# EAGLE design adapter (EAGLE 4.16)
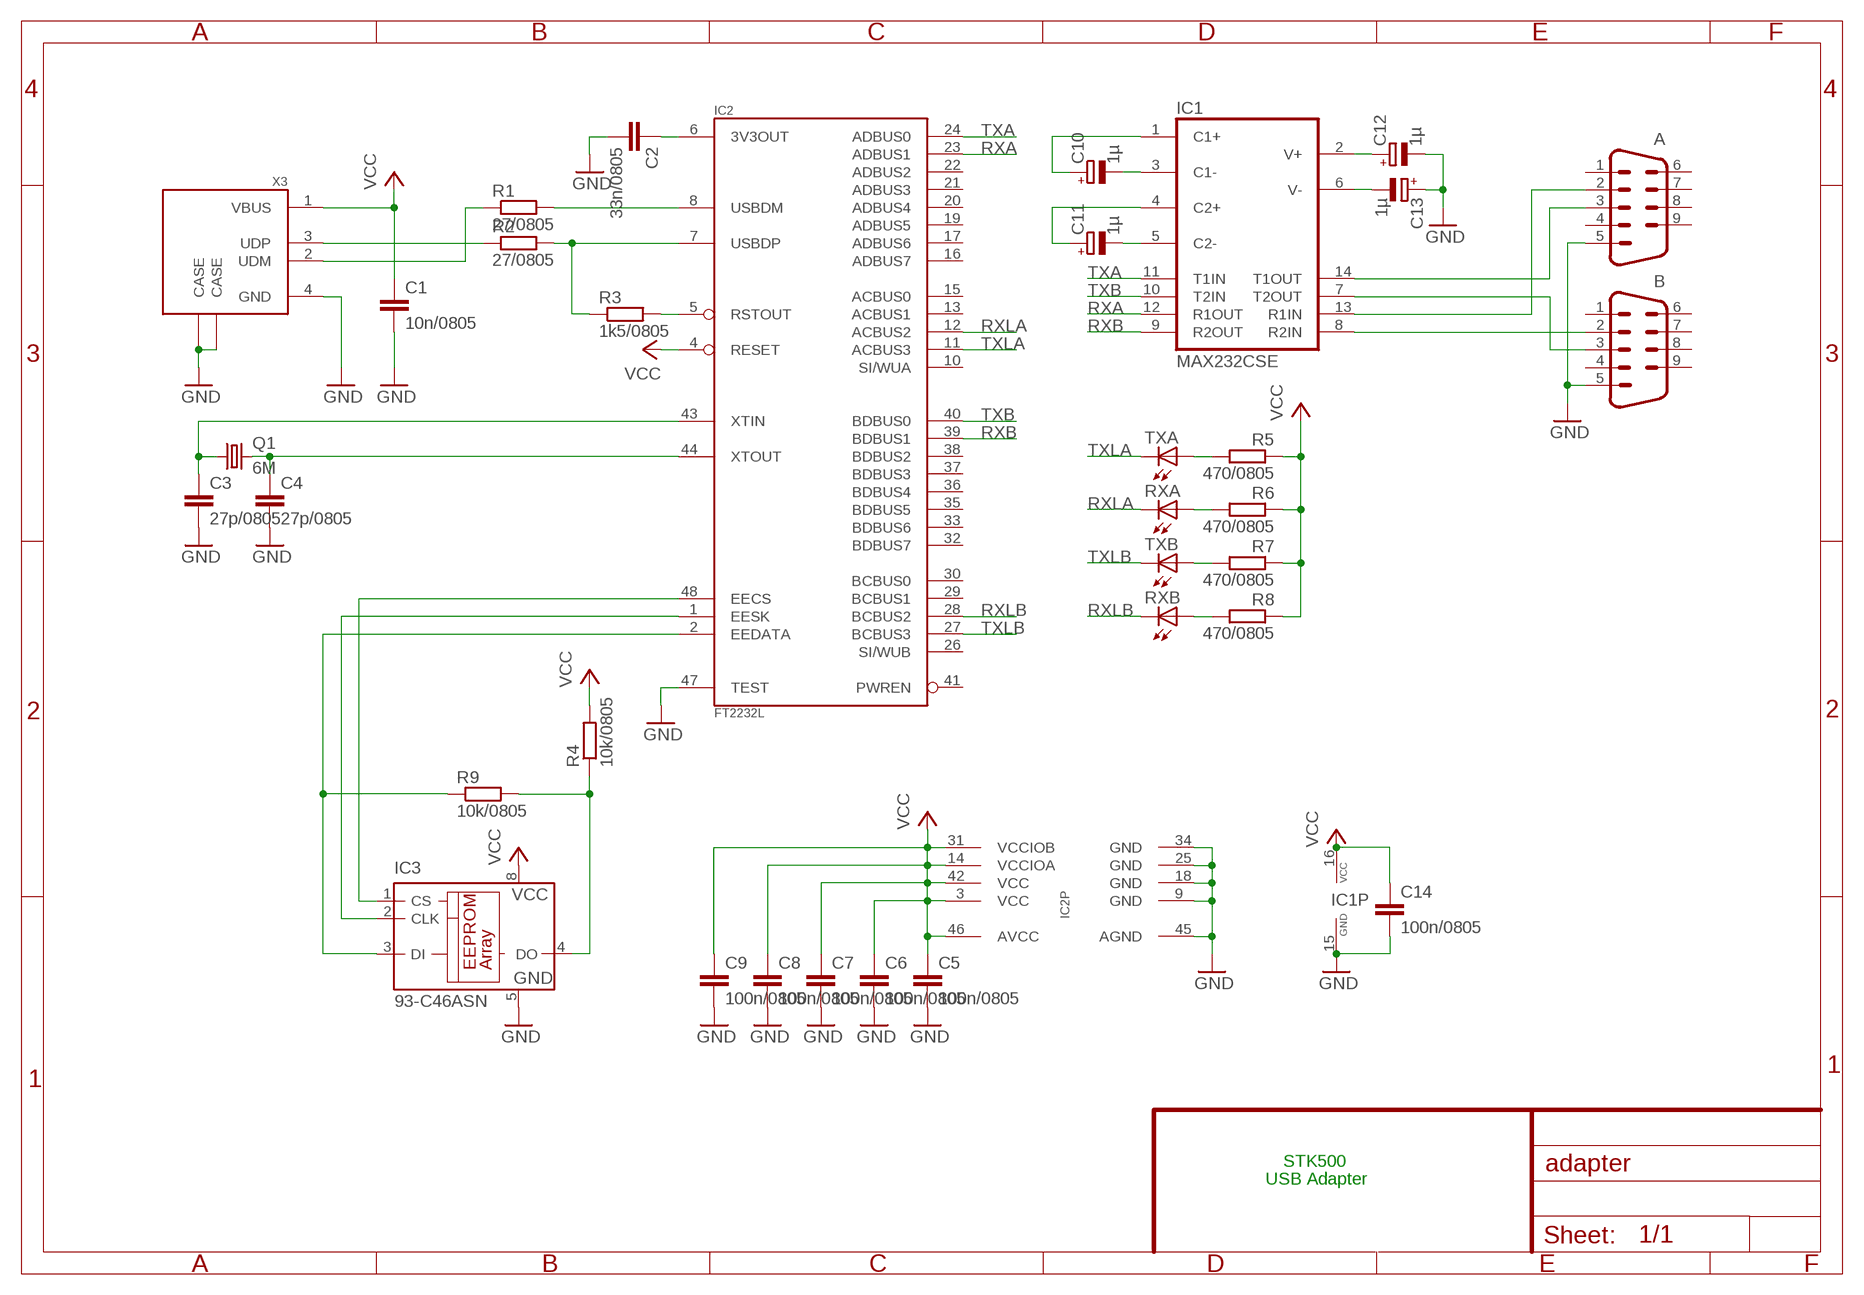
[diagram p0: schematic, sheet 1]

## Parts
A  M09HP  [M09HP]
B  M09HP  [M09HP]
C1  10n/0805  C-EUC0805  [C0805]
C2  33n/0805  C-EUC0805  [C0805]
C3  27p/0805  C-EUC0805  [C0805]
C4  27p/0805  C-EUC0805  [C0805]
C5  100n/0805  C-EUC0805  [C0805]
C6  100n/0805  C-EUC0805  [C0805]
C7  100n/0805  C-EUC0805  [C0805]
C8  100n/0805  C-EUC0805  [C0805]
C9  100n/0805  C-EUC0805  [C0805]
C10  1µ  CPOL-EU153CLV-0405  [153CLV-0405]
C11  1µ  CPOL-EU153CLV-0405  [153CLV-0405]
C12  1µ  CPOL-EU153CLV-0405  [153CLV-0405]
C13  1µ  CPOL-EU153CLV-0405  [153CLV-0405]
C14  100n/0805  C-EUC0805  [C0805]
IC1  MAX232CSE  [SO16]
IC2  FT2232L  [LQFP48]
IC3  93-C46ASN  [SO-08]
Q1  6M  CRYSTALHC49S  [HC49/S]
R1  27/0805  R-EU_R0805  [R0805]
R2  27/0805  R-EU_R0805  [R0805]
R3  1k5/0805  R-EU_R0805  [R0805]
R4  10k/0805  R-EU_R0805  [R0805]
R5  470/0805  R-EU_R0805  [R0805]
R6  470/0805  R-EU_R0805  [R0805]
R7  470/0805  R-EU_R0805  [R0805]
R8  470/0805  R-EU_R0805  [R0805]
R9  10k/0805  R-EU_R0805  [R0805]
RXA  LEDCHIPLED_1206  [CHIPLED_1206]
RXB  LEDCHIPLED_1206  [CHIPLED_1206]
TXA  LEDCHIPLED_1206  [CHIPLED_1206]
TXB  LEDCHIPLED_1206  [CHIPLED_1206]
X3  PN61729  [PN61729]

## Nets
GND: A.5 B.5 C1.2 C2.2 C3.2 C4.2 C5.2 C6.2 C7.2 C8.2 C9.2 C12.- C13.+ C14.2 IC1.15(GND) IC2.9(GND) IC2.18(GND) IC2.25(GND) IC2.34(GND) IC2.45(AGND) IC2.47(TEST) IC3.5(GND) X3.4(GND) X3.CASE@1(CASE) X3.CASE@2(CASE)
N$1: IC2.5(RSTOUT) R3.2
N$2: IC2.8(USBDM) R1.2
N$3: IC2.7(USBDP) R2.2 R3.1
N$4: IC2.48(EECS) IC3.1(CS)
N$5: R1.1 X3.2(UDM)
N$6: R2.1 X3.3(UDP)
N$7: A.3 IC1.14(T1OUT)
N$8: B.3 IC1.7(T2OUT)
N$9: C2.1 IC2.6(3V3OUT)
N$10: C3.1 IC2.43(XTIN) Q1.1
N$11: C4.1 IC2.44(XTOUT) Q1.2
N$12: IC2.1(EESK) IC3.2(CLK)
N$13: A.2 IC1.13(R1IN)
N$14: B.2 IC1.8(R2IN)
N$15: C10.+ IC1.1(C1+)
N$16: C10.- IC1.3(C1-)
N$17: C11.+ IC1.4(C2+)
N$18: C11.- IC1.5(C2-)
N$19: C12.+ IC1.2(V+)
N$20: C13.- IC1.6(V-)
N$21: IC2.2(EEDATA) IC3.3(DI) R9.1
N$22: IC3.4(DO) R4.1 R9.2
N$24: R5.2 TXA.A
N$25: R6.2 RXA.A
N$26: R7.2 TXB.A
N$27: R8.2 RXB.A
RXA: IC1.12(R1OUT) IC2.23(ADBUS1)
RXB: IC1.9(R2OUT) IC2.39(BDBUS1)
RXLA: IC2.12(ACBUS2) RXA.C
RXLB: IC2.28(BCBUS2) RXB.C
TXA: IC1.11(T1IN) IC2.24(ADBUS0)
TXB: IC1.10(T2IN) IC2.40(BDBUS0)
TXLA: IC2.11(ACBUS3) TXA.C
TXLB: IC2.27(BCBUS3) TXB.C
VCC: C1.1 C5.1 C6.1 C7.1 C8.1 C9.1 C14.1 IC1.16(VCC) IC2.3(VCC) IC2.4(RESET) IC2.14(VCCIOA) IC2.31(VCCIOB) IC2.42(VCC) IC2.46(AVCC) IC3.8(VCC) R4.2 R5.1 R6.1 R7.1 R8.1 X3.1(VBUS)
Unconnected: A.1 A.4 A.6 A.7 A.8 A.9 B.1 B.4 B.6 B.7 B.8 B.9 IC2.10(SI/WUA) IC2.13(ACBUS1) IC2.15(ACBUS0) IC2.16(ADBUS7) IC2.17(ADBUS6) IC2.19(ADBUS5) IC2.20(ADBUS4) IC2.21(ADBUS3) IC2.22(ADBUS2) IC2.26(SI/WUB) IC2.29(BCBUS1) IC2.30(BCBUS0) IC2.32(BDBUS7) IC2.33(BDBUS6) IC2.35(BDBUS5) IC2.36(BDBUS4) IC2.37(BDBUS3) IC2.38(BDBUS2) IC2.41(PWREN)

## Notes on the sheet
- STK500
- USB Adapter

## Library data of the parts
A B = con-subd:M09: SUB-D
C1-C9 C14 = rcl:C-EU: CAPACITOR, European symbol
C10-C13 = rcl:CPOL-EU: POLARIZED CAPACITOR, European symbol
IC1 = maxim:MAX232*: RS232 Transreceiver 2 Transmitter / 2 Receiver
IC2 = ftdichip:FT2232
IC3 = microchip:93-*: Serial EEPROM 512 x 8 bit/256 x 16 bit/1 K/4 K, 5.0 V, Microwire
Q1 = crystal:CRYSTAL: CRYSTAL
R1-R9 = rcl:R-EU_: RESISTOR, European symbol
RXA RXB TXA TXB = led:LED: LED
X3 = con-berg:PN61729: BERG USB connector

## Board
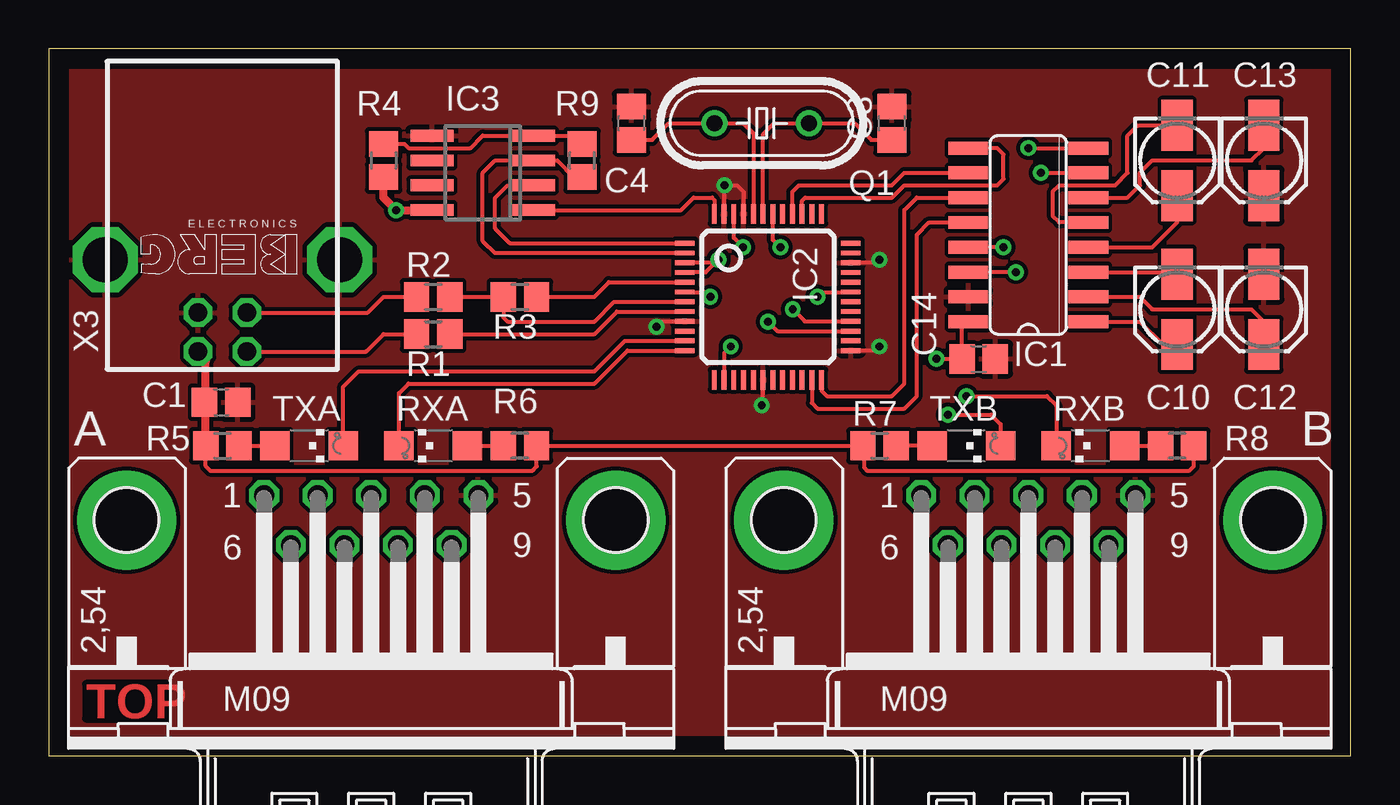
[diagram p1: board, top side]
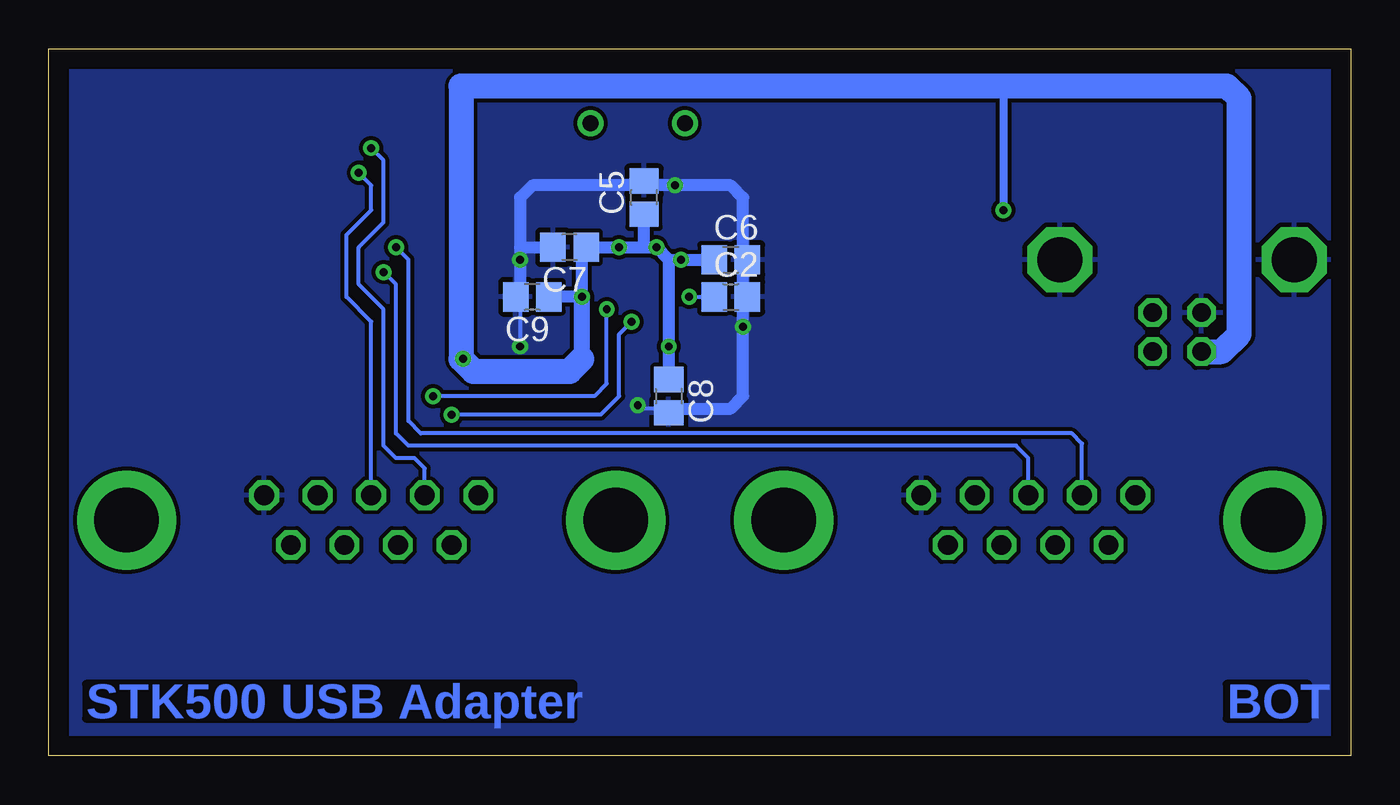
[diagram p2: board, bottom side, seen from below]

Size 66.67 x 36.2 mm. Coordinates in mm from the lower left corner, seen from the top.
Outline: 0,0 66.67,0 66.67,36.2 0,36.2 0,0
Copper layers (1*16): Top 0.035mm / dielectric 1.5mm / Bottom 0.035mm
Design rules "default": minimum track width 8mil, minimum drill 12mil, track to track 8mil, track to pad 8mil, pad to pad 8mil, via to via 8mil, smd to smd 8mil, copper to edge 40mil, drill to drill 8mil, minimum pad ring 10mil, minimum via ring 8mil, stop-mask expansion 4mil, vias tented up to drill 0mil, thermal gap 10mil

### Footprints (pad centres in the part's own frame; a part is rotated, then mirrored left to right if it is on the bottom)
M09HP = drill 1.016 octagon: 1 -5.486,1.27; 2 -2.743,1.27; 3 0,1.27; 4 2.743,1.27; 5 5.486,1.27; 6 -4.115,-1.27; 7 -1.372,-1.27; 8 1.372,-1.27; 9 4.115,-1.27 | drill 3.302 pad 5.08 round: G1 -12.522,0; G2 12.522,0
C0805 = smd 1.3 x 1.5: 1 -0.85,0; 2 0.85,0
153CLV-0405 = smd 2.6 x 1.6: + 1.8,0; - -1.8,0
SO16 = smd 0.66 x 2.032: 1 -4.445,-3.073; 2 -3.175,-3.073; 3 -1.905,-3.073; 4 -0.635,-3.073; 5 0.635,-3.073; 6 1.905,-3.073; 7 3.175,-3.073; 8 4.445,-3.073; 9 4.445,3.073; 10 3.175,3.073; 11 1.905,3.073; 12 0.635,3.073; 13 -0.635,3.073; 14 -1.905,3.073; 15 -3.175,3.073; 16 -4.445,3.073
LQFP48 = smd 0.25 x 1: 1 -2.75,-4.25; 2 -2.25,-4.25; 3 -1.75,-4.25; 4 -1.25,-4.25; 5 -0.75,-4.25; 6 -0.25,-4.25; 7 0.25,-4.25; 8 0.75,-4.25; 9 1.25,-4.25; 10 1.75,-4.25; 11 2.25,-4.25; 12 2.75,-4.25; 25 2.75,4.25; 26 2.25,4.25; 27 1.75,4.25; 28 1.25,4.25; 29 0.75,4.25; 30 0.25,4.25; 31 -0.25,4.25; 32 -0.75,4.25; 33 -1.25,4.25; 34 -1.75,4.25; 35 -2.25,4.25; 36 -2.75,4.25 | smd 1 x 0.25: 13 4.25,-2.75; 14 4.25,-2.25; 15 4.25,-1.75; 16 4.25,-1.25; 17 4.25,-0.75; 18 4.25,-0.25; 19 4.25,0.25; 20 4.25,0.75; 21 4.25,1.25; 22 4.25,1.75; 23 4.25,2.25; 24 4.25,2.75; 37 -4.25,2.75; 38 -4.25,2.25; 39 -4.25,1.75; 40 -4.25,1.25; 41 -4.25,0.75; 42 -4.25,0.25; 43 -4.25,-0.25; 44 -4.25,-0.75; 45 -4.25,-1.25; 46 -4.25,-1.75; 47 -4.25,-2.25; 48 -4.25,-2.75
SO-08 = smd 0.6 x 2.2: 1 -1.905,-2.6; 2 -0.635,-2.6; 3 0.635,-2.6; 4 1.905,-2.6; 5 1.905,2.6; 6 0.635,2.6; 7 -0.635,2.6; 8 -1.905,2.6
HC49/S = drill 0.813 round: 1 -2.413,0; 2 2.413,0
R0805 = smd 1.3 x 1.5: 1 -0.85,0; 2 0.85,0
CHIPLED_1206 = smd 1.5 x 1.5: A 0,-1.75; C 0,1.75
PN61729 = drill 0.95 octagon: 1 1.25,4.71; 2 -1.25,4.71; 3 -1.25,2.71; 4 1.25,2.71 | drill 2.3 octagon: CASE@1 -6,0; CASE@2 6,0

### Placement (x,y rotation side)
A  16.51,12.06 0 top
B  50.16,12.06 0 top
C1  8.83,18.1 0 top
C2  31.75,23.5 0 bottom
C3  43.18,32.38 90 top
C4  29.84,32.38 90 top
C5  36.2,28.57 90 bottom
C6  31.75,25.4 0 bottom
C7  40.01,26.04 180 bottom
C8  34.92,18.41 270 bottom
C9  41.91,23.5 180 bottom
C10  57.78,22.86 270 top
C11  57.78,30.48 270 top
C12  62.23,22.86 270 top
C13  62.23,30.48 270 top
C14  47.62,20.32 0 top
IC1  50.16,26.67 90 top
IC2  36.83,23.5 270 top
IC3  22.23,29.84 90 top
Q1  36.51,32.38 180 top
R1  19.68,21.59 0 top
R2  19.68,23.5 0 top
R3  24.13,23.5 0 top
R4  17.14,30.48 270 top
R5  8.89,15.88 0 top
R6  24.13,15.88 180 top
R7  42.55,15.88 0 top
R8  57.78,15.88 180 top
R9  27.3,30.48 90 top
RXA  19.68,15.88 90 top
RXB  53.34,15.88 90 top
TXA  13.34,15.88 270 top
TXB  46.99,15.88 270 top
X3  8.89,25.4 180 top

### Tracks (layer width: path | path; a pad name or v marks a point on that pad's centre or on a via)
GND  (via drill 0.41)
  Top 0.203: IC2.18 36.58,18.16 v36.51,17.94 | IC2.45 35.58,28.87 35.24,29.21 v34.61,29.21 34.58,28.86 IC2.47 | IC2.34 42.39,25.25 v42.55,25.4 | IC2.25 42.34,20.75 v42.55,20.95 | IC2.9 31.39,22.25 v31.11,21.97
  Bottom 0.203: 34.92,17.78 36.35,17.78 v36.51,17.94 | v36.51,17.94 | 42.55,23.5 v42.55,20.95
  Bottom 0.61: 36.2,29.21 C5.2 | 36.2,29.21 v34.61,29.21 31.75,29.21 31.11,28.57 31.11,25.4 | 31.11,23.5 v31.11,21.97 31.11,18.41 31.75,17.78 34.92,17.78 C8.2 | 31.11,23.5 31.11,25.4 | 31.11,23.5 C2.2 | 31.11,25.4 C6.2 | C9.2 42.55,23.5 v42.55,25.4 42.55,26.04 | 36.2,29.21 41.91,29.21 42.55,28.57 42.55,26.04 | 42.55,26.04 C7.2
  pour Top: 0.64,0.64 66.04,0.64 66.04,35.56 0.64,35.56
  pour Bottom: 0.64,35.56 65.84,35.56 66.04,35.36 66.04,0.64 0.84,0.64 0.64,0.84
N$1
  Top 0.203: R3.2 27.94,23.5 28.69,24.25 IC2.5
N$2
  Top 0.203: R1.2 27.94,21.59 29.09,22.75 IC2.8
N$3
  Top 0.203: R2.2 R3.1 23.28,22.44 23.5,22.23 27.94,22.23 28.96,23.25 IC2.7
N$4
  Top 0.203: IC3.1 32.38,27.94 33.02,28.57 33.97,28.57 34.08,28.47 IC2.48
N$5
  Top 0.203: X3.2 16.25,20.69 17.14,21.59 R1.1
N$6
  Top 0.203: X3.3 16.34,22.69 17.14,23.5 R2.1
N$7  (via drill 0.41)
  Top 0.203: 46.99,24.77 IC1.14 v49.53,24.77
  Bottom 0.203: v49.53,24.77 48.9,24.13 48.9,16.51 48.26,15.88 17.14,15.88 16.51,15.24 A.3
N$8  (via drill 0.41)
  Top 0.203: v50.8,29.84 IC1.7
  Bottom 0.203: v50.8,29.84 50.16,29.21 50.16,27.94 51.44,26.67 51.44,23.5 50.16,22.23 B.3
N$9  (via drill 0.41)
  Top 0.203: IC2.6 33.63,23.75 v33.88,23.5
  Bottom 0.203: 32.38,23.5 C2.1 v33.88,23.5
N$10
  Top 0.203: IC2.43 36.58,31.82 37.15,32.38 38.73,32.38 | C3.1 42.12,31.54 41.27,32.38 38.73,32.38 | 38.73,32.38 Q1.1
N$11
  Top 0.203: IC2.44 36.08,31.86 35.56,32.38 34.29,32.38 | C4.1 30.9,31.54 31.75,32.38 34.29,32.38 | 34.29,32.38 Q1.2
N$12
  Top 0.203: IC3.2 23.5,29.21 22.86,28.57 22.86,26.99 23.6,26.25 IC2.1
N$13  (via drill 0.41)
  Top 0.203: 46.99,26.04 IC1.13 v48.9,26.04
  Bottom 0.203: v48.9,26.04 48.26,25.4 48.26,17.14 47.62,16.51 14.29,16.51 13.77,15.99 A.2
N$14  (via drill 0.41)
  Top 0.203: v50.16,31.11 IC1.8
  Bottom 0.203: v50.16,31.11 49.53,30.48 49.53,27.3 50.8,26.04 50.8,24.13 49.53,22.86 49.53,15.88 48.9,15.24 47.94,15.24 47.42,14.72 B.2
N$15
  Top 0.203: IC1.1 55.88,22.23 57.05,21.06 C10.+
N$16
  Top 0.203: C10.- 57.68,24.77 IC1.3
N$17
  Top 0.203: C11.+ 57.78,27.3 56.52,26.04 IC1.4
N$18
  Top 0.203: IC1.5 51.75,27.3 51.44,27.62 51.44,28.89 51.75,29.21 54.61,29.21 55.24,29.84 55.24,31.75 55.77,32.28 C11.-
N$19
  Top 0.203: C12.+ 62.23,22.23 61.59,22.86 56.52,22.86 55.88,23.5 IC1.2
N$20
  Top 0.203: IC1.6 55.24,28.57 55.88,29.21 55.88,29.84 56.52,30.48 61.59,30.48 62.23,31.11 C13.-
N$21
  Top 0.203: R9.1 26.89,29.63 26.04,30.48 IC3.3 22.86,30.48 22.23,29.84 22.23,26.35 22.83,25.75 IC2.2
N$22
  Top 0.203: R9.2 26.89,31.75 IC3.4 22.23,31.75 21.59,31.11 18.41,31.11 18.2,31.33 R4.1
N$24
  Top 0.203: R5.2 TXA.A
N$25
  Top 0.203: 23.5,15.88 R6.2 RXA.A
N$26
  Top 0.203: TXB.A R7.2
N$27
  Top 0.203: 57.15,15.88 R8.2 RXB.A
RXA
  Top 0.203: IC2.23 39.08,18.07 39.37,17.78 43.81,17.78 44.45,18.41 44.45,26.67 45.09,27.3 IC1.12
RXB
  Top 0.203: IC1.9 48.58,31.11 48.9,30.8 48.9,29.53 48.58,29.21 43.81,29.21 43.18,28.57 38.73,28.57 38.58,28.42 IC2.39
RXLA
  Top 0.203: IC2.12 29.64,20.75 27.94,19.05 18.41,19.05 17.93,18.57 RXA.C
RXLB  (via drill 0.41)
  Top 0.203: RXB.C 51.59,17.94 51.12,18.41 v46.99,18.41 | IC2.28 38.72,22.25 v38.1,22.86
  Bottom 0.203: v46.99,18.41 38.73,18.41 38.1,19.05 v38.1,22.86
TXA
  Top 0.203: IC2.24 39.58,18.68 39.85,18.41 43.18,18.41 43.81,19.05 43.81,27.94 44.45,28.57 IC1.11
TXB
  Top 0.203: IC2.40 38.08,28.87 38.42,29.21 43.18,29.21 43.81,29.84 IC1.10
TXLA
  Top 0.203: IC2.11 29.5,21.25 27.94,19.68 15.88,19.68 15.09,18.89 TXA.C
TXLB  (via drill 0.41)
  Top 0.203: TXB.C 48.74,16.98 48.26,17.46 v46.04,17.46 | IC2.27 37.31,21.75 v36.83,22.23
  Bottom 0.203: v36.83,22.23 37.47,21.59 37.47,18.41 38.42,17.46 v46.04,17.46
VCC  (via drill 0.41)
  Top 0.203: IC2.3 34.13,25.25 v34.29,25.4 33.63,24.75 IC2.4 | IC2.14 34.58,20.61 v34.92,20.95 | IC2.31 39.62,23.75 v39.37,23.5 | IC2.42 37.08,26.42 v37.47,26.04 | IC2.46 35.08,26.52 v35.56,26.04 | IC1.16 46.99,22.23 46.77,22.01 C14.1 v45.47,20.32 | R5.1 8.04,14.82 8.26,14.61 24.77,14.61 24.98,14.82 R6.1 R7.1 41.75,15.88 41.75,14.76 41.91,14.61 58.42,14.61 58.63,14.82 R8.1
  Top 0.406: R4.2 17.14,28.57 v17.78,27.94 IC3.8 | X3.1 7.64,20.66 7.62,20.64 8.04,20.22 8.04,18.41 | R5.1 8.04,18.41 | 8.04,18.41 8.26,18.41 7.98,18.14 C1.1
  Bottom 0.203: C8.1 34.92,19.05 | C9.1 41.27,23.5 | 45.56,20.32 v45.47,20.32
  Bottom 0.406: 17.78,34.29 v17.78,27.94
  Bottom 0.61: C6.1 v34.29,25.4 34.92,25.4 | C8.1 v34.92,20.95 34.92,25.4 | C9.1 v39.37,23.5 39.37,25.82 C7.1 v37.47,26.04 36.2,26.04 | 36.2,26.04 C5.1 | 36.2,26.04 v35.56,26.04 34.92,25.4
  Bottom 0.813: 39.37,20.32 v39.37,23.5
  Bottom 1.27: X3.1 6.62,20.69 5.71,21.59 5.71,33.66 6.35,34.29 17.78,34.29 45.56,34.29 45.56,20.32 44.93,19.68 40.01,19.68 39.37,20.32

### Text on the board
Top: TOP
Bottom: BOT | STK500 USB Adapter
Measures: 66.675mm | 36.195mm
